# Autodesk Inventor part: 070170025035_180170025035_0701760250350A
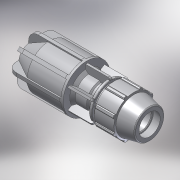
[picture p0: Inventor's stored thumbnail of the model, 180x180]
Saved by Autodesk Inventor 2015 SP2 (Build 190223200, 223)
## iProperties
Created: 2017-02
Part Number: 070170025035_180170025035_0701760250350A
Material: PVC-Piping
Description: PLASSON PLASS4 COUPLING 27-35*25
Document SubType Name: Modeling
Designer: KIM
Mass: 92.6774 g
Surface Area: 199.44 cm^2
Volume: 66.1981 cm^3
Density: 1.4 g/cm^3
Appearance: Smooth - White
Author: KIM
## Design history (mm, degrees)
derived "070170.ipt"
feature "Solid1::070170.ipt"
tag "TaggingFeature1"
body "Solid1"
other parameters: "d2" = 25, "d4" = 12.85714, "d5" = 20.3, "d7" = 54, "d8" = 34.23797, "d9" = 11.57143, "d11" = 4.5, "d12" = 43.2, "d13" = 120 deg, "d14" = 37.5, "d15" = 12 deg, "d16" = 48.6, "d18" = 1.25, "d19" = 35 deg, "d20" = 17.5 deg, "d21" = 50.22, "d23" = 0, "d25" = 360 deg, "d27" = 1.08, "d42" = 26.1, "d43" = 1.62, "d46" = 0.75, "d53" = 0.5, "d67" = 2.7, "d70" = 22.5, "d71" = 58, "d74" = 180 deg, "d75" = 35, "d76" = 83, "d80" = 22.5, "d84" = 78.85, "d85" = 135 deg, "d86" = 4.15, "d89" = 4.15, "d90" = 135 deg, "d94" = 4.15, "d97" = 4.32, "d98" = 0, "d100" = 360 deg, "d102" = 91.3, "d103" = 16.6, "d104" = 6.64, "d105" = 0, "d112" = 108, "d113" = 30.6, "d114" = 72, "d115" = 49.8, "d116" = 108, "d117" = 4.5, "d118" = 27, "d119" = 2.7, "d120" = 0, "d121" = 2.7, "d123" = 360 deg, "d_" = 25, "E_" = 54, "A_" = 81, "l_" = 58, "d_1" = 35, "E_1" = 83, "d106" = 34.23797
